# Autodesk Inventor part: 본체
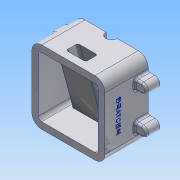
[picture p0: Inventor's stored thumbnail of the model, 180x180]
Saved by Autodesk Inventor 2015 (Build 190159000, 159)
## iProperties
Created: 2018-01
Part Number: 본체
Material: 알루미늄 6061
Document SubType Name: Modeling
Designer: user
Density: 2.7 g/cm^3
Appearance: 알루미늄 - 평지
Mass: 995.264 g
Surface Area: 834.391 cm^2
Volume: 368.616 cm^3
Author: user
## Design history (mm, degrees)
sketch "스케치1"
  geometry: L1 (55, 55)-(-55, 55); L2 (-55, 55)-(-55, -55); L3 (-55, -55)-(55, -55); L4 (55, -55)-(55, 55); 3 further points
  constraints: 8 end point, 2 midpoint, 2 parallel, 1 horizontal, 1 horizontal alignment, 1 perpendicular, 1 vertical alignment
  dimensions: "d0" = 110 distance of L1.start L1.end; "d1" = 110 distance of L1.end L2.end
extrude "돌출1" new body sketch "스케치1" distance "d2" = 65; taper "d3" = 0 deg
sketch "스케치2"
  geometry: L1 (-55, -55)-(55, -55) reference; L2 (55, -55)-(55, 55) reference; L3 (55, 55)-(-55, 55) reference; L4 (55, -55)-(55, 55) reference; L5 (65, -20.5)-(55, -20.5); L6 (65, -35.5)-(55, -35.5); L7 (65, 20.5)-(55, 20.5); L8 (65, 35.5)-(55, 35.5); L9 (55, 35.5)-(55, 20.5); L10 (55, -20.5)-(55, -35.5); A1 r 7.5 centre (65, 28) between (65, 20.5) and (65, 35.5); A2 r 7.5 centre (65, -28) between (65, -35.5) and (65, -20.5); 1 further point
  constraints: 12 end point, 4 point on circle, 4 point on line, 4 tangent, 3 perpendicular, 2 centre point, 2 collinear, 1 horizontal
  dimensions: "d4" = 56 distance of A1.centre A2.centre; "d5" = 15 diameter of A1; "d6" = 15 diameter of A2; "d7" = 10 distance from line of L2 A2.centre; "d8" = 27 distance from line of A2.centre L1; "d9" = 27 distance from line of L3 A1.centre
extrude "돌출2" join sketch "스케치2" distance "d10" = 20; taper "d11" = 0 deg
sketch "스케치3"
  geometry: L1 (-55, -55)-(55, -55) reference; L2 (55, -20.5)-(55, 20.5) reference; L3 (55, 55)-(-55, 55) reference; L4 (-55, 20.5)-(-55, -20.5) reference; L5 (-45, -45)-(45, -45); L6 (45, -45)-(45, 45); L7 (45, 45)-(-45, 45); L8 (-45, 45)-(-45, -45); 1 further point
  constraints: 8 end point, 2 parallel, 1 horizontal, 1 perpendicular
  dimensions: "d12" = 10 distance between parallel lines of L7 L3; "d13" = 10 distance between parallel lines of L4 L8; "d14" = 10 distance between parallel lines of L1 L5; "d15" = 10 distance between parallel lines of L2 L6
extrude "돌출3" cut sketch "스케치3" stored distance "d16" = 20; taper "d17" = 0 deg
sketch "스케치4"
  geometry: L1 (65, 45)-(65, -45) reference; L2 (65, -35)-(30, -35); L3 (30, -35)-(8.564, 45); L4 (65, 45)-(0, 45) reference; L5 (0, -45)-(0, 45) reference; L6 (0, -55)-(65, -55) reference; L7 (65, -35)-(65, 45); L8 (8.564, 45)-(65, 45); 1 further point
  constraints: 8 end point, 2 point on line, 1 collinear, 1 horizontal, 1 perpendicular
  dimensions: "d18" = 105 deg angle of L3 L4; "d19" = 30 distance from line of L2.end L5; "d20" = 20 distance between parallel lines of L6 L2
extrude "돌출4" join sketch "스케치4" stored distance "d21" = 50; taper "d22" = 0 deg
sketch "스케치5"
  geometry: L1 (-55, -55)-(55, -55) reference; L2 (55, 55)-(-55, 55) reference; L3 (0, -55)-(0, 55); L4 (0, -55)-(-7.5, -55); L5 (-7.5, -36)-(-16, -36); L6 (-16, -36)-(-16, -22); L7 (-16, -22)-(-20, -22); L8 (-20, -22)-(-20, 25); L9 (-20, 25)-(-15, 25); L10 (-15, 30)-(0, 30); L11 (-15, 30)-(-15, 25); L12 (-7.5, -36)-(-7.5, -55); 1 further point
  constraints: 20 end point, 3 perpendicular, 2 horizontal, 2 midpoint, 2 point on line, 2 vertical, 1 parallel
  dimensions: "d23" = 15 diameter of L12 L3; "d24" = 32 diameter of L6 L3; "d25" = 40 diameter of L8 L3; "d26" = 30 diameter of L11 L3; "d27" = 19 distance between parallel lines of L5 L1; "d28" = 14 distance of L5.end L6.end; "d29" = 47 distance of L7.end L8.end; "d30" = 5 distance of L10.start L9.end
revolve "회전1" sketch "스케치5" stored, may be unused: angle "d31" = 90 deg
sketch "스케치6"
  geometry: L1 (30, -35)-(8.564, 45) reference; L2 (31.157, -20)-(11.061, 55); L3 (0, 55)-(65, 55) reference; L4 (29.061, 55)-(39.243, 17); L5 (65, 22)-(45, 22) reference; L6 (65, -25)-(45, -25) reference; L7 (39.243, 17)-(65, 17); L8 (65, -20)-(31.157, -20); L9 (65, 22)-(65, -25) reference; L10 (65, -20)-(65, 17); L11 (29.061, 55)-(11.061, 55); 1 further point
  constraints: 12 end point, 4 point on line, 2 horizontal, 1 collinear, 1 parallel, 1 vertical
  dimensions: "d32" = 5 distance between parallel lines of L2 L1; "d33" = 75 deg angle of L3 L4; "d34" = 18 distance of L2.end L4.start; "d38" = 5 distance between parallel lines of L5 L7; "d39" = 5 distance between parallel lines of L6 L8
extrude "돌출5" cut sketch "스케치6" stored distance "d40" = 30; taper "d41" = 0 deg
hole "구멍1" diameter "d44" = 3.242; stored, may be unused: countersink angle "d48" = 90 deg, drill point angle "d50" = 118 deg; dims "d42" = 10, "d43" = 10, "d45" = 9, "d46" = 4, "d47" = 2, "d49" = 11
hole "구멍2" diameter "d53" = 3.242; stored, may be unused: countersink angle "d57" = 90 deg, drill point angle "d59" = 118 deg; dims "d51" = 10, "d52" = 10, "d54" = 9, "d55" = 4, "d56" = 2, "d58" = 11
fillet "모깎기1" dims "d60" = 15
fillet "모깎기2" dims "d61" = 1
fillet "모깎기3" dims "d62" = 3
fillet "모깎기4" dims "d63" = 3
chamfer "모따기1" distance "d64" = 1; stored, may be unused: second distance "d65" = 2, angle "d66" = 45 deg
fillet "모깎기5" dims "d67" = 5
fillet "모깎기6" dims "d68" = 3
fillet "모깎기7" dims "d69" = 3
fillet "모깎기8" dims "d70" = 3
fillet "모깎기9" dims "d71" = 3
fillet "모깎기10" dims "d72" = 3
fillet "모깎기11" dims "d73" = 3
fillet "모깎기13" dims "d75" = 3
fillet "모깎기14" dims "d76" = 3
node "작업 평면1"
sketch "스케치7"
  geometry: L1 (-15, 65)-(-15, 0) reference; L2 (95, 0)-(80, 0) reference; 2 further points
  constraints: 1 other
  dimensions: "d78" = 55 distance from line of L1 point (40, 20); "d79" = 20 distance from line of L2 point (40, 20)
feature "엠보싱1" sketch "스케치7" dims "d0" = 110, "d1" = 110, "d4" = 56, "d5" = 15, "d6" = 15, "d7" = 10, "d8" = 27, "d9" = 27, "d80" = 0.5, "d81" = 0
node "솔리드1"
mirror "대칭1"
mirror "대칭2"
other parameters: "d77" = 18.75
